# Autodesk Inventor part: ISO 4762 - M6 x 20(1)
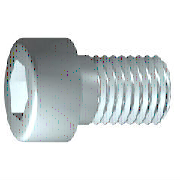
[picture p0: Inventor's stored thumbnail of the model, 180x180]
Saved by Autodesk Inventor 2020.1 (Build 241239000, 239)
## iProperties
Created: 2019-01
Part Number: ISO 4762 - M6 x 20(1)
Material: Edelstahl, 440C
Description: Innensechskantschraube
Document SubType Name: Modeling
Standard: ISO 4762
Designer: lutzd
Standard Revision: Fourth edition 2004-03-01
Standards Organization: ISO
Language: de-DE
Size Designation: M6 x 20
Categories: <MemberInstance><Categories><Category DisplayName="Verbindungselemente" InternalName="e4da775c-781d-43d5-af7c-5136215cf5a6" Mnemonic="FSTN"><Category DisplayNam
Mass: 7.37801 g
Surface Area: 7.641 cm^2
Volume: 0.952002 cm^3
Density: 7.75 g/cm^3
Appearance: Halbpoliert
IsCustomPart: 0
Author: lutzd
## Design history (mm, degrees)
body "Solid1"
sketch "Skizze1"
  geometry: L1 (-1.333, 0)-(20, 0); L2 (20, 0)-(20, 3); L3 (20, 3)-(2.5, 3); L4 (2.5, 3)-(1.886, 3); L5 (1.886, 3)-(0, 3); L6 (0, 3)-(0, 5); L7 (0, 5)-(-6, 5); L8 (-6, 5)-(-6, 2.887); L9 (-6, 2.887)-(-3, 2.887); L10 (-3, 2.887)-(-1.333, 0); L11 (-11.2, 0)-(25.2, 0) reference; L12 (0, -1)-(0, 6) reference; L13 (2.5, 3)-(0, 3)
  constraints: 22 end point, 6 parallel, 2 collinear, 2 perpendicular, 1 horizontal, 1 point on line
  dimensions: "d1" = 17.5 distance from line of L3.end L2 (= GEL); "d2" = 0.61355 distance of L4.end L3.end (computed from GAL); "d3" = 6 distance between parallel lines of L8 L6 (= KOH); "d4" = 3 distance of L8.end L9.end (= INTI); "d5" = 60 deg angle of L10 L1; "d6" = 6 diameter of L3 L1 (= GD); "d7" = 6 diameter of L5 L1 (= BDM); "d8" = 5.7735 diameter of L9 L1 (= 1.1547 x SW); "d9" = 10 diameter of L7 L1 (= KOD); "d26" = 20 distance between parallel lines of L12 L2 (= NLG)
workplane "Work Plane1"
fillet "Fillet2" dims "d30" = 0.1 (= R)
revolve "Körper" stored, may be unused: angle "d10" = 90 deg
sketch "Skizze2"
  geometry: L1 (0, -7)-(0, 7) reference; L2 (-7, 0)-(7, 0) reference; L3 (2.887, 0)-(1.443, -2.5); L4 (1.443, -2.5)-(-1.443, -2.5); L5 (-1.443, -2.5)-(-2.887, 0); L6 (-2.887, 0)-(-1.443, 2.5); L7 (-1.443, 2.5)-(1.443, 2.5); L8 (1.443, 2.5)-(2.887, 0); 2 further points
  constraints: 12 end point, 1 coincident, 1 horizontal alignment, 1 point on line, 12 other
extrude "Loch" join sketch "Skizze2" stored distance "d11" = 10; taper "d12" = 0 deg
fillet "Rundung1" dims "d17" = 0.6 (= RR)
feature "Gewinde" dims "d13" = 17.5 (= GEL), "d14" = 0
chamfer "Fase1" distance "d15" = 0.61345 (= -0.5 x SPD + 0.5 x GD); stored, may be unused: second distance "d16" = 0.61345 (= GUL), angle "d27" = 45 deg
other parameters: "GD" = 6 [user parameter; used in 2 equation terms], "NLG" = 20 [user parameter; used in 1 equation term], "GEL" = 17.5 [user parameter; used in 2 equation terms], "KOD" = 10 [user parameter; used in 1 equation term], "KOH" = 6 [user parameter; used in 1 equation term], "INTI" = 3 [user parameter; used in 1 equation term], "GAL" = 0.61345 (= 0.61345 x PTC) [user parameter; used in 1 equation term], "GUL" = 0.61345 (= 0.61345 x PTC) [user parameter; used in 1 equation term], "BDM" = 6 (= NND) [user parameter; used in 1 equation term], "SW" = 5 [user parameter; used in 2 equation terms], "RR" = 0.6 [user parameter; used in 1 equation term], "SPD" = 4.7731 (= NND - 1.2269 x PTC) [user parameter; used in 1 equation term], "d19" = 0, "d28" = 0, "d29" = 0, "R" = 0.1 [user parameter; used in 1 equation term], "TOA" = 30 deg [user parameter], "GD1" = 4.7731 (= THREADDIA - 1.2269 x PTC) [user parameter], "THREADDIA" = 6 [user parameter; used in 1 equation term], "FAWI" = 45 deg [user parameter], "PTC" = 1 [user parameter; used in 5 equation terms], "NND" = 6 [user parameter; used in 2 equation terms], "E0" = 5.775 (= 1.155 x SW) [user parameter]
